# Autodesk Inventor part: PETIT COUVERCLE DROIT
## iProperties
Created: 2004-11
Part Number: PETIT COUVERCLE DROIT
Document SubType Name: Modeling
Designer: Bruno
Manufacturer: Standard
Standards Organization: Custom
Author: Bruno
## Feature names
1. Base1
